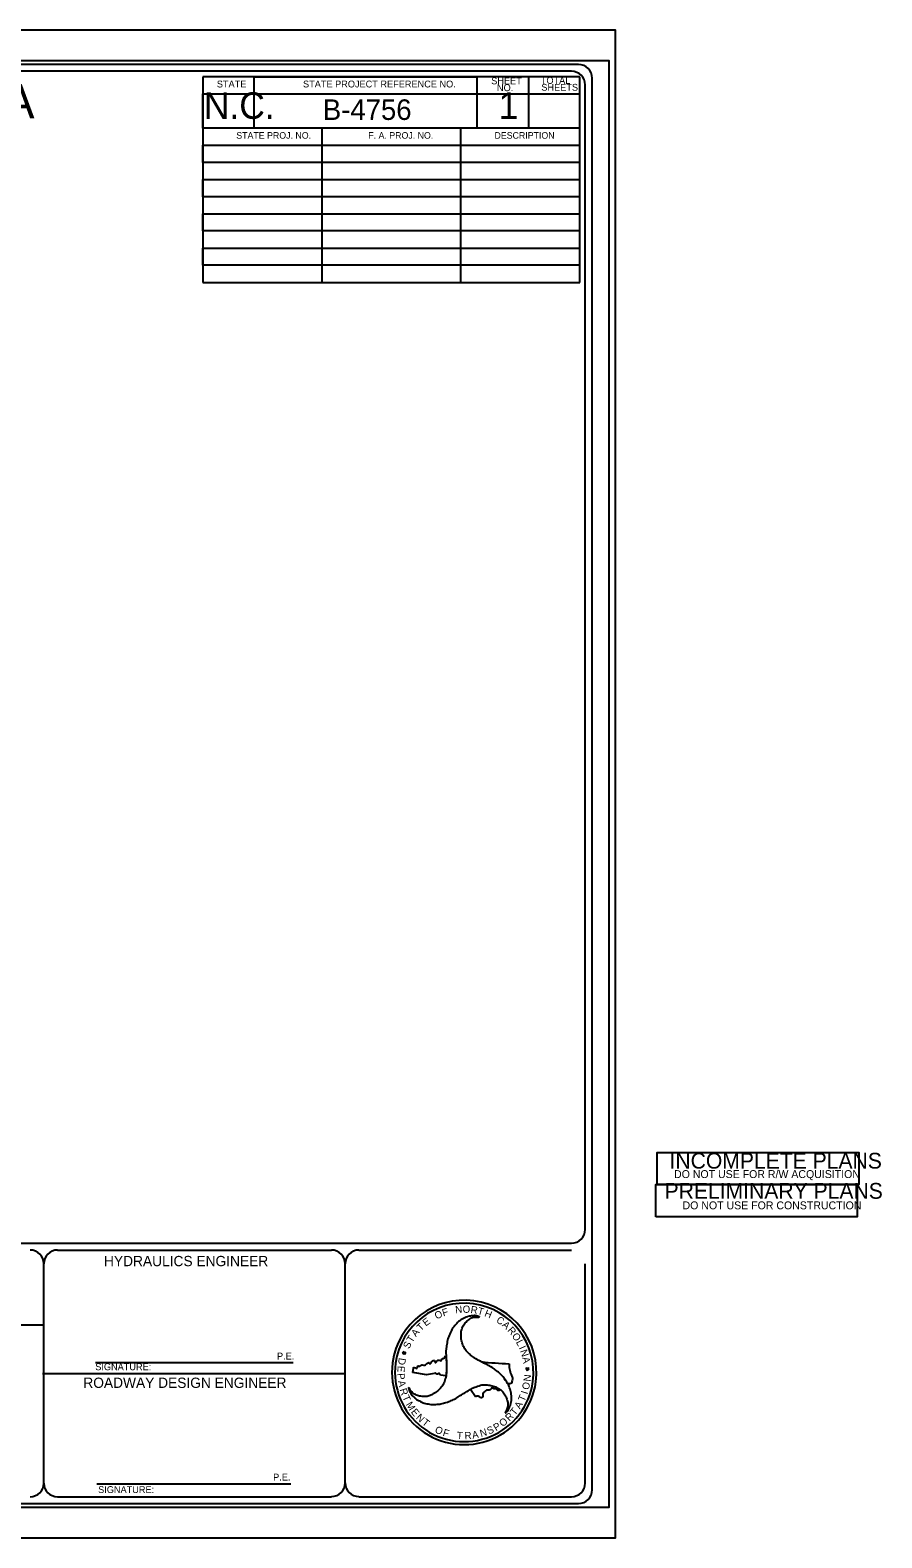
# Model space of a CAD drawing. Extents: x 2431000 to 2534000, y 645879 to 714000.
# Drawn here: x 2465110 to 2465731, y 678900 to 680000 of the extents above; entities that cross this region are included whole.
import ezdxf

# ---------------------------------------------------------------- set-up
doc = ezdxf.new("R2010")
doc.units = 0
for name, color, linetype in [('Sheet Data Field CELL', 7, 'Continuous'), ('Sheet Plot Border Inside CELL', 7, 'Continuous'), ('Sheet Plot Border Outside CELL', 7, 'Continuous'), ('Sheet Title CELL', 7, 'Continuous')]:
    doc.layers.add(name, color=color, linetype=linetype)

msp = doc.modelspace()

# ---------------------------------------------------------------- linework, layer by layer
at = {"layer": 'Sheet Plot Border Inside CELL'}
msp.add_lwpolyline([(2463866.2, 678922.5), (2465532.2, 678922.5), (2465532.2, 679977.5), (2463866.2, 679977.5)], close=True, dxfattribs=at)
at = {"layer": 'Sheet Plot Border Outside CELL'}
msp.add_lwpolyline([(2463853.2, 678900), (2465536.7, 678900), (2465536.7, 680000), (2463853.2, 680000)], close=True, dxfattribs=at)
at = {"layer": 'Sheet Title CELL'}
for p, q in [((2465510.7, 679966), (2465235.7, 679966)), ((2465235.7, 679966), (2465235.7, 679816)), ((2465273.2, 679928.5), (2465273.2, 679966)), ((2465273.2, 679966), (2465435.7, 679966)), ((2465435.7, 679966), (2465435.7, 679928.5)), ((2465510.7, 679966), (2465473.2, 679966)), ((2465473.2, 679966), (2465473.2, 679928.5)), ((2465510.7, 679953.5), (2465510.7, 679966)), ((2465510.7, 679816), (2465510.7, 679966)), ((2465235.7, 679928.5), (2465235.7, 679953.5)), ((2465235.7, 679953.5), (2465510.7, 679953.5)), ((2465510.7, 679928.5), (2465235.7, 679928.5)), ((2465327.3, 679928.5), (2465273.2, 679928.5)), ((2465322.7, 679816), (2465322.7, 679928.5)), ((2465435.7, 679928.5), (2465419, 679928.5)), ((2465423.8, 679928.5), (2465423.8, 679816)), ((2465510.7, 679916), (2465510.7, 679928.5)), ((2465235.7, 679903.5), (2465235.7, 679916)), ((2465235.7, 679916), (2465510.7, 679916)), ((2465510.7, 679903.5), (2465235.7, 679903.5)), ((2465510.7, 679891), (2465510.7, 679903.5)), ((2465235.7, 679878.5), (2465235.7, 679891)), ((2465235.7, 679891), (2465510.7, 679891)), ((2465510.7, 679878.5), (2465235.7, 679878.5)), ((2465510.7, 679866), (2465510.7, 679878.5)), ((2465235.7, 679853.5), (2465235.7, 679866)), ((2465235.7, 679866), (2465510.7, 679866)), ((2465510.7, 679853.5), (2465235.7, 679853.5)), ((2465510.7, 679841), (2465510.7, 679853.5)), ((2465235.7, 679828.5), (2465235.7, 679841)), ((2465235.7, 679841), (2465510.7, 679841)), ((2465510.7, 679828.5), (2465235.7, 679828.5)), ((2465510.7, 679816), (2465510.7, 679828.5)), ((2465235.7, 679816), (2465510.7, 679816)), ((2465235.7, 679816), (2465327.3, 679816)), ((2465419, 679816), (2465510.7, 679816)), ((2464084.7, 679115), (2465504.7, 679115)), ((2465129.7, 679110), (2465329.5, 679110)), ((2465349.5, 679110), (2465504.7, 679110)), ((2465119.7, 678940), (2465119.7, 679100)), ((2465339.5, 678940), (2465339.5, 679100)), ((2465119.7, 679055.2), (2464814.7, 679055.2)), ((2465437.5, 679061.4), (2465437.4, 679061.3)), ((2465437.5, 679061.4), (2465437.4, 679061.3)), ((2465382, 679034.8), (2465381.3, 679035.4)), ((2465381.3, 679035.4), (2465382.2, 679035.3)), ((2465381.6, 679034), (2465382, 679034.8)), ((2465382.3, 679034.4), (2465381.6, 679034)), ((2465382.2, 679035.3), (2465382.6, 679036.1)), ((2465383, 679033.8), (2465382.3, 679034.4)), ((2465382.6, 679036.1), (2465382.8, 679035.2)), ((2465382.8, 679035.2), (2465383.7, 679035.1)), ((2465383.7, 679035.1), (2465382.9, 679034.7)), ((2465382.9, 679034.7), (2465383, 679033.8)), ((2465118.8, 679020), (2465339.5, 679020)), ((2465157.5, 679028), (2465301.7, 679028)), ((2465389, 679020.7), (2465389.5, 679023.9)), ((2465398.8, 679019), (2465389, 679020.7)), ((2465404.7, 679019.9), (2465398.8, 679019)), ((2465438.8, 679028.6), (2465438.8, 679028.6)), ((2465472.3, 679023.6), (2465471.4, 679023.8)), ((2465471.4, 679023.8), (2465472, 679023.1)), ((2465472, 679023.1), (2465471.7, 679022.3)), ((2465471.7, 679022.3), (2465472.4, 679022.7)), ((2465472.7, 679024.4), (2465472.3, 679023.6)), ((2465472.4, 679022.7), (2465473.1, 679022.1)), ((2465472.9, 679023.6), (2465472.7, 679024.4)), ((2465473.7, 679023.5), (2465472.9, 679023.6)), ((2465472.9, 679023), (2465473.7, 679023.5)), ((2465473.1, 679022.1), (2465472.9, 679023)), ((2465413.1, 679018.1), (2465409, 679018.7)), ((2465434.6, 679002.9), (2465430.9, 679008.3)), ((2465430.9, 679008.3), (2465430.9, 679008.3)), ((2465478.7, 679013.8), (2465478.7, 679013.8)), ((2465158.4, 678939.4), (2465299.9, 678939.4))]:
    msp.add_line(p, q, dxfattribs=at)
for points in [[(2465509.7, 679975), (2464029.7, 679975)], [(2465504.7, 679970), (2464084.7, 679970)], [(2465514.7, 679125), (2465514.7, 679960)], [(2465519.7, 678935), (2465519.7, 679965)], [(2465514.7, 678940), (2465514.7, 679100)], [(2464029.7, 678925), (2465509.7, 678925)], [(2465129.7, 678930), (2465329.5, 678930)], [(2465349.5, 678930), (2465504.7, 678930)]]:
    msp.add_lwpolyline(points, dxfattribs=at)
for points in [[(2465567.3, 679157.7), (2465567.3, 679181.2), (2465714.3, 679181.2), (2465714.3, 679157.7)], [(2465566.1, 679134.2), (2465566.1, 679157.7), (2465713.1, 679157.7), (2465713.1, 679134.2)]]:
    msp.add_lwpolyline(points, close=True, dxfattribs=at)
for centre, radius, start, end in [((2465504.7, 679960), 10, 0, 90), ((2465509.7, 679965), 10, 0, 90), ((2465504.7, 679125), 10, 270, 0), ((2465109.7, 679100), 10, 0, 90), ((2465129.7, 679100), 10, 90, 180), ((2465329.5, 679100), 10, 0, 90), ((2465349.5, 679100), 10, 90, 180), ((2465426.4, 679020.7), 52.7, 352.4211, 172.4211), ((2465426.4, 679020.7), 50.5, 352.4211, 172.4211), ((2465470.1, 679304.7), 277.9, 258.0996, 258.1992), ((2465426.4, 679020.7), 52.7, 172.4211, 352.4211), ((2465426.4, 679020.7), 50.5, 172.4211, 352.4211), ((2465470.1, 679304.7), 277.9, 263.5387, 267.7447), ((2465109.7, 678940), 10, 270, 0), ((2465129.7, 678940), 10, 180, 270), ((2465329.5, 678940.1), 10, 270, 0), ((2465349.5, 678940.1), 10, 180, 270), ((2465504.7, 678940), 10, 270, 0), ((2465509.7, 678935), 10, 270, 0)]:
    msp.add_arc(centre, radius, start, end, dxfattribs=at)
for points in [[(2465437.4, 679061.3), (2465436.2, 679061.8), (2465432.7, 679062.1), (2465429.1, 679061.4), (2465428.7, 679061.3), (2465426.8, 679060.6), (2465424.8, 679059.5), (2465421.6, 679057.2), (2465419, 679054.1), (2465417.9, 679052.9), (2465417.1, 679051.2), (2465415.4, 679047.7), (2465414.3, 679044.2), (2465413.5, 679040.1), (2465413.1, 679036.4), (2465413.2, 679032.6), (2465413.4, 679028.7), (2465413.4, 679025), (2465413.4, 679021.2), (2465413, 679017.4), (2465412.9, 679017.1), (2465411.7, 679013.2), (2465409.6, 679009.9), (2465407.2, 679007.3), (2465405.8, 679006.1), (2465403.8, 679005), (2465402.7, 679004.3), (2465400.2, 679003.4), (2465396.5, 679003.1), (2465393, 679003.7), (2465390.1, 679004.9), (2465387.6, 679007.1), (2465385.7, 679009.8)], [(2465456.2, 678990.9), (2465457.1, 678991.6), (2465459.1, 678994.5), (2465460.4, 678998), (2465460.5, 678998.3), (2465460.8, 679000.3), (2465460.8, 679002.7), (2465460.5, 679006.6), (2465459.1, 679010.4), (2465458.6, 679011.9), (2465457.5, 679013.5), (2465455.3, 679016.7), (2465452.9, 679019.4), (2465449.7, 679022.1), (2465446.7, 679024.3), (2465443.3, 679026.2), (2465439.9, 679027.9), (2465436.7, 679029.7), (2465433.3, 679031.7), (2465430.4, 679033.9), (2465430.1, 679034.2), (2465427.3, 679037.2), (2465425.5, 679040.6), (2465424.4, 679044), (2465424.2, 679045.8), (2465424.2, 679048.1), (2465424.1, 679049.4), (2465424.6, 679052), (2465426.1, 679055.4), (2465428.4, 679058), (2465431, 679060), (2465434.1, 679061.1), (2465437.4, 679061.3), (2465437.5, 679061.4)], [(2465389.5, 679023.9), (2465389.4, 679024.2), (2465390, 679024.4), (2465391.4, 679023.6), (2465392.2, 679024.2), (2465392.3, 679024.8), (2465392.9, 679025.4), (2465393.9, 679025), (2465395, 679026.1), (2465395.8, 679026.2), (2465397.6, 679025.9), (2465400, 679027.8), (2465400.9, 679027.8), (2465401, 679027.2), (2465401.5, 679027), (2465402.7, 679028.6), (2465402.9, 679028.8), (2465404.7, 679029.3), (2465405.1, 679028.9), (2465405.1, 679028.1), (2465405.3, 679027.9), (2465405.9, 679028.2), (2465406.7, 679029.1), (2465408.2, 679029.6), (2465409.7, 679029.2), (2465410.1, 679030.4), (2465412.1, 679031.4), (2465412.5, 679032.1), (2465412.7, 679032.8)], [(2465413.2, 679032.7), (2465413.2, 679032.6), (2465413.4, 679028.7), (2465413.4, 679025), (2465413.4, 679021.2), (2465413.1, 679018.1)], [(2465409, 679018.7), (2465408.7, 679019.5), (2465407.9, 679019.9), (2465406.8, 679019.4), (2465406, 679019.6), (2465405.1, 679020.4), (2465404.7, 679019.9)], [(2465458.2, 679012.5), (2465457.5, 679013.5), (2465455.3, 679016.7), (2465452.9, 679019.4), (2465449.7, 679022.1), (2465446.7, 679024.3), (2465443.3, 679026.2), (2465439.9, 679027.9), (2465438.8, 679028.6)], [(2465459.1, 679027), (2465459.4, 679023.4), (2465460.7, 679019.1), (2465461.6, 679016.7), (2465461.3, 679014.7), (2465460.5, 679012.5), (2465458.3, 679012.6)], [(2465385.7, 679009.8), (2465386, 679008.6), (2465387.4, 679005.4), (2465389.8, 679002.6), (2465390.1, 679002.4), (2465391.6, 679001), (2465393.7, 678999.9), (2465397.3, 678998.2), (2465401.1, 678997.5), (2465402.8, 678997.2), (2465404.7, 678997.3), (2465408.5, 678997.6), (2465412.1, 678998.4), (2465416.1, 678999.8), (2465419.4, 679001.3), (2465422.7, 679003.3), (2465426, 679005.4), (2465429.2, 679007.3), (2465432.5, 679009.2), (2465436, 679010.6), (2465436.3, 679010.7), (2465440.3, 679011.7), (2465444.1, 679011.5), (2465447.6, 679010.7), (2465449.4, 679010.1), (2465451.3, 679008.9), (2465452.5, 679008.3), (2465454.5, 679006.6), (2465456.6, 679003.6), (2465457.8, 679000.3), (2465458.2, 678997), (2465457.6, 678993.8), (2465456.2, 678990.9)], [(2465430.9, 679008.3), (2465432.5, 679009.2), (2465436, 679010.6), (2465436.3, 679010.7), (2465440.3, 679011.7), (2465444.1, 679011.5), (2465447.6, 679010.7), (2465449.4, 679010.1), (2465451.3, 679008.9), (2465452.4, 679008.4)], [(2465452.4, 679008.4), (2465451.8, 679007.5), (2465451, 679007.6), (2465449.7, 679008.8), (2465448, 679008.7), (2465447.3, 679009.3), (2465446.8, 679009.4), (2465445.4, 679008), (2465443.6, 679007.8), (2465440.7, 679006.2), (2465439.9, 679005.1), (2465439.8, 679002.6), (2465439.1, 679002.2), (2465438.3, 679002.4), (2465436.7, 679003.3), (2465434.6, 679002.9)]]:
    msp.add_spline(points, degree=3, dxfattribs=at)

# ---------------------------------------------------------------- texts
at = {"layer": 'Sheet Data Field CELL'}
msp.add_text('B-4756', height=15, dxfattribs=at).set_placement((2465323.3, 679934.5))
at = {"layer": 'Sheet Title CELL'}
for s, height, p in [('SHEET', 5, (2465446.1, 679960.5)), ('TOTAL', 5, (2465482.3, 679960.8)), ('STATE OF NORTH CAROLINA', 25, (2464641.1, 679935.7)), ('N.C.', 19.35, (2465236.4, 679935.3)), ('STATE', 5, (2465245.9, 679958.2)), ('STATE PROJECT REFERENCE NO.', 5, (2465308.8, 679958.2)), ('NO.', 5, (2465450.3, 679955.5)), ('1', 19.4, (2465451.5, 679935.3)), ('SHEETS', 5, (2465482.7, 679955.8)), ('STATE PROJ. NO.', 4.8, (2465260.1, 679920.8)), ('F. A. PROJ. NO.', 4.8, (2465356.4, 679920.8)), ('DESCRIPTION', 4.8, (2465448.5, 679920.8)), ('INCOMPLETE PLANS', 11.52, (2465576.2, 679169.4)), ('DO NOT USE FOR R/W ACQUISITION', 5.76, (2465579.5, 679162.5)), ('PRELIMINARY PLANS', 11.52, (2465572.6, 679147.4)), ('DO NOT USE FOR CONSTRUCTION', 5.76, (2465585.7, 679139.7)), (' HYDRAULICS ENGINEER', 7.5, (2465160.8, 679098.2)), ('P.E.', 5, (2465289.8, 679030.1)), ('SIGNATURE:', 5, (2465157.2, 679022.3)), ('ROADWAY DESIGN ENGINEER', 7.499, (2465148.5, 679009.4)), ('P.E.', 5, (2465287, 678941.8)), ('SIGNATURE:', 5, (2465159.3, 678932.7))]:
    msp.add_text(s, height=height, dxfattribs=at).set_placement(p)
for s, height, rotation, p in [('O', 5.26, 24.6387, (2465406.2, 679059.3)), ('F', 5.27, 17.4918, (2465411.2, 679061.5)), ('N', 5.26, 5.4049, (2465420.1, 679063.8)), ('O', 5.27, 357.9068, (2465425.2, 679064.3)), ('R', 5.26, 351.2969, (2465430.8, 679064.1)), ('T', 5.27, 344.6472, (2465435.7, 679063.3)), ('H', 5.25, 337.5625, (2465440.7, 679061.9)), ('T', 5.24, 43.6937, (2465394.7, 679050.5)), ('E', 5.24, 36.5781, (2465398.4, 679054.1)), ('C', 5.24, 325.2202, (2465449.3, 679057.8)), ('A', 5.25, 317.7231, (2465453.6, 679054.8)), ('R', 5.25, 311.3592, (2465457.6, 679051.2)), ('S', 5.25, 64.1774, (2465386.2, 679037.5)), ('T', 5.27, 57.8012, (2465388.4, 679042)), ('A', 5.27, 50.7489, (2465391.2, 679046.3)), ('O', 5.27, 304.2396, (2465460.9, 679047.4)), ('L', 5.24, 298.0059, (2465464, 679042.8)), ('D', 5.26, 260.2741, (2465378.8, 679031.6)), ('I', 5.26, 294.0166, (2465466.1, 679038.7)), ('N', 5.25, 288.3165, (2465467.1, 679036.4)), ('A', 5.26, 280.8845, (2465468.7, 679031.5)), ('E', 5.23, 266.562, (2465377.9, 679025.6)), ('P', 5.26, 274.0944, (2465377.6, 679019.9)), ('A', 5.25, 280.687, (2465378, 679014.3)), ('R', 5.26, 287.7556, (2465379.2, 679008.2)), ('O', 5.24, 77.3812, (2465473.5, 679007.7)), ('N', 5.26, 84.6293, (2465474.8, 679013.9)), ('T', 5.25, 294.4062, (2465381.1, 679002.7)), ('M', 5.24, 301.6412, (2465383.6, 678997.3)), ('A', 5.27, 59.5113, (2465467.1, 678993.6)), ('T', 5.25, 66.5957, (2465470.2, 678999)), ('I', 5.27, 72.2456, (2465472.5, 679004.4)), ('E', 5.24, 309.108, (2465387.2, 678991.7)), ('N', 5.27, 316.0795, (2465390.8, 678987.3)), ('T', 5.25, 322.9215, (2465395.2, 678983.2)), ('O', 5.27, 38.1354, (2465454.4, 678980.7)), ('R', 5.26, 45.3245, (2465459.4, 678984.7)), ('T', 5.24, 51.4242, (2465463.4, 678988.9)), ('O', 5.25, 336.2252, (2465404.5, 678977.1)), ('F', 5.25, 343.3904, (2465410.4, 678974.6)), ('T', 5.24, 356.2997, (2465420.9, 678972.2)), ('R', 5.26, 3.2563, (2465426.8, 678971.9)), ('A', 5.24, 10.0094, (2465432.6, 678972.3)), ('N', 5.24, 17.041, (2465438.7, 678973.5)), ('S', 5.23, 24.2515, (2465444.4, 678975.3)), ('P', 5.25, 31.4434, (2465449.6, 678977.7))]:
    msp.add_text(s, height=height, rotation=rotation, dxfattribs=at).set_placement(p)

doc.saveas('drawing.dxf')
